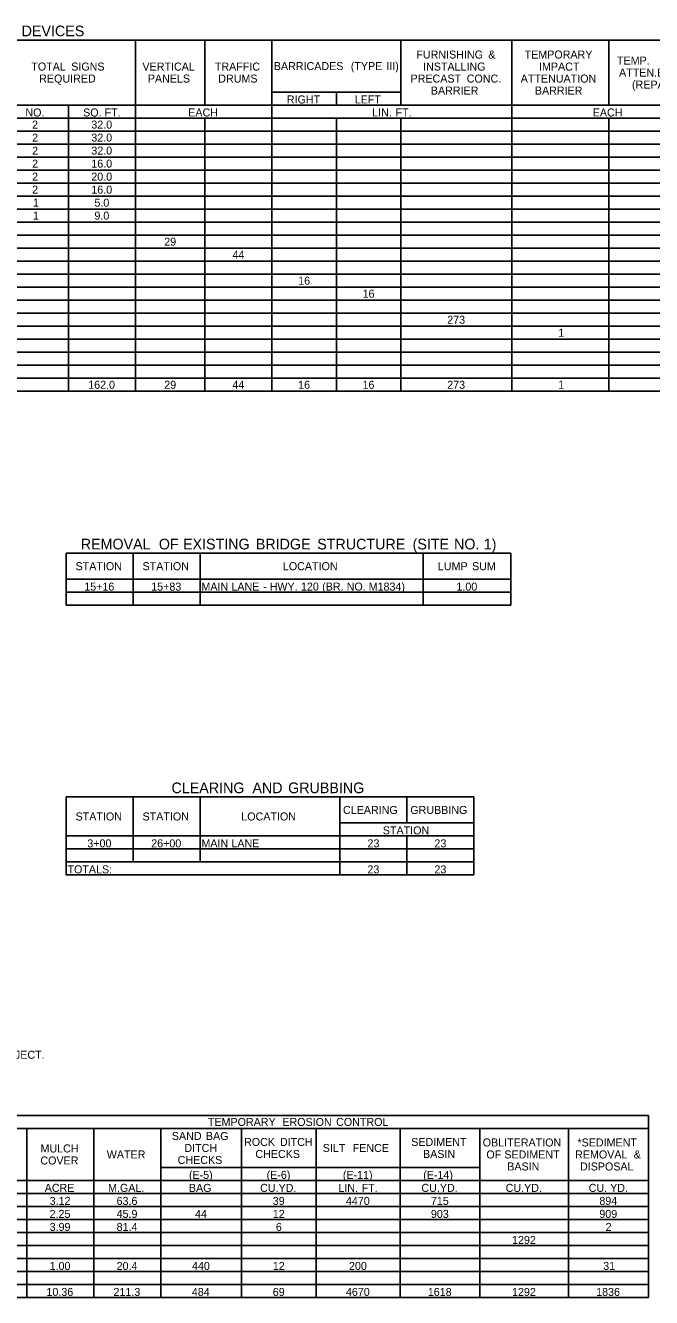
# Model space of a CAD drawing. Extents: x 1940653 to 1945779, y 534266 to 535271.
# Drawn here: x 1941239 to 1941662, y 534410 to 535268 of the extents above; entities that cross this region are included whole.
import ezdxf

# ---------------------------------------------------------------- set-up
doc = ezdxf.new("R2010")
doc.units = 0
doc.layers.add('Default', color=7, linetype='Continuous')
doc.layers.add('R_Logo', color=7, linetype='Continuous')

msp = doc.modelspace()

# ---------------------------------------------------------------- linework, layer by layer
at = {"layer": 'Default'}
for p, q in [((1940658.64, 535258.6), (1941697.16, 535258.6)), ((1941313.26, 535021.67), (1941313.26, 535258.6)), ((1941360.2, 535214.72), (1941360.2, 535258.6)), ((1941405.39, 535021.67), (1941405.39, 535258.6)), ((1941492.27, 535214.72), (1941492.27, 535258.6)), ((1941567.29, 535021.67), (1941567.29, 535258.6)), ((1941632.67, 535214.72), (1941632.67, 535258.6)), ((1941405.39, 535223.5), (1941492.27, 535223.5)), ((1941448.83, 535214.72), (1941448.83, 535223.5)), ((1941448.83, 535214.72), (1941448.83, 535223.5)), ((1941222.87, 535214.72), (1941697.16, 535214.72)), ((1941268.07, 535021.67), (1941268.07, 535214.72)), ((1941405.39, 535214.72), (1941448.83, 535214.72)), ((1941405.39, 535021.67), (1941405.39, 535214.72)), ((1941448.83, 535214.72), (1941697.16, 535214.72)), ((1941567.29, 535021.67), (1941567.29, 535214.72)), ((1941170.66, 535205.95), (1941697.16, 535205.95)), ((1941268.07, 535021.67), (1941268.07, 535205.95)), ((1941313.26, 535021.67), (1941313.26, 535205.95)), ((1941360.2, 535021.67), (1941360.2, 535205.95)), ((1941360.2, 535021.67), (1941360.2, 535205.95)), ((1941448.83, 535021.67), (1941448.83, 535205.95)), ((1941448.83, 535021.67), (1941448.83, 535205.95)), ((1941492.27, 535021.67), (1941492.27, 535205.95)), ((1941492.27, 535021.67), (1941492.27, 535205.95)), ((1941632.67, 535021.67), (1941632.67, 535205.95)), ((1941632.67, 535021.67), (1941632.67, 535205.95)), ((1940658.64, 535197.17), (1941697.16, 535197.17)), ((1940658.64, 535188.4), (1941697.16, 535188.4)), ((1940658.64, 535179.62), (1941697.16, 535179.62)), ((1940658.64, 535170.85), (1941697.16, 535170.85)), ((1940658.64, 535162.07), (1941697.16, 535162.07)), ((1940658.64, 535153.3), (1941697.16, 535153.3)), ((1940658.64, 535144.52), (1941697.16, 535144.52)), ((1940658.64, 535135.75), (1941697.16, 535135.75)), ((1940658.64, 535126.97), (1941697.16, 535126.97)), ((1940658.64, 535118.2), (1941697.16, 535118.2)), ((1940658.64, 535109.42), (1941697.16, 535109.42)), ((1940658.64, 535100.65), (1941697.16, 535100.65)), ((1940658.64, 535091.87), (1941697.16, 535091.87)), ((1940658.64, 535083.1), (1941697.16, 535083.1)), ((1940658.64, 535074.32), (1941697.16, 535074.32)), ((1940658.64, 535065.55), (1941697.16, 535065.55)), ((1940658.64, 535056.77), (1941697.16, 535056.77)), ((1940658.64, 535048), (1941697.16, 535048)), ((1940658.64, 535039.22), (1941697.16, 535039.22)), ((1940658.64, 535030.45), (1941697.16, 535030.45)), ((1940658.64, 535021.67), (1941697.16, 535021.67)), ((1941266.54, 534912.46), (1941566.65, 534912.46)), ((1941266.54, 534877.36), (1941266.54, 534912.46)), ((1941266.54, 534877.36), (1941266.54, 534912.46)), ((1941311.73, 534877.36), (1941311.73, 534912.46)), ((1941356.92, 534877.36), (1941356.92, 534912.46)), ((1941507.41, 534877.36), (1941507.41, 534912.46)), ((1941566.65, 534877.36), (1941566.65, 534912.46)), ((1941566.65, 534877.36), (1941566.65, 534912.46)), ((1941266.54, 534894.91), (1941566.65, 534894.91)), ((1941311.73, 534877.36), (1941311.73, 534894.91)), ((1941356.92, 534877.36), (1941356.92, 534894.91)), ((1941507.41, 534877.36), (1941507.41, 534894.91)), ((1941266.54, 534886.13), (1941566.65, 534886.13)), ((1941266.54, 534877.36), (1941566.65, 534877.36)), ((1941266.54, 534748.03), (1941541.64, 534748.03)), ((1941266.54, 534695.38), (1941266.54, 534748.03)), ((1941266.54, 534695.38), (1941266.54, 534748.03)), ((1941311.73, 534704.15), (1941311.73, 534748.03)), ((1941356.92, 534704.15), (1941356.92, 534748.03)), ((1941451.25, 534695.38), (1941451.25, 534748.03)), ((1941496.45, 534730.48), (1941496.45, 534748.03)), ((1941541.64, 534695.38), (1941541.64, 534748.03)), ((1941541.64, 534730.48), (1941541.64, 534748.03)), ((1941451.25, 534730.48), (1941541.64, 534730.48)), ((1941451.25, 534704.15), (1941451.25, 534730.48)), ((1941266.54, 534721.7), (1941541.64, 534721.7)), ((1941311.73, 534704.15), (1941311.73, 534721.7)), ((1941356.92, 534704.15), (1941356.92, 534721.7)), ((1941496.45, 534695.38), (1941496.45, 534721.7)), ((1941496.45, 534695.38), (1941496.45, 534721.7)), ((1941541.64, 534704.15), (1941541.64, 534721.7)), ((1941266.54, 534712.93), (1941541.64, 534712.93)), ((1941266.54, 534704.15), (1941541.64, 534704.15)), ((1941356.92, 534704.15), (1941541.64, 534704.15)), ((1941266.54, 534695.38), (1941541.64, 534695.38)), ((1940660.36, 534533.19), (1941659.39, 534533.19)), ((1941659.39, 534410.34), (1941659.39, 534533.19)), ((1940953.44, 534524.41), (1941659.39, 534524.41)), ((1941239.95, 534410.34), (1941239.95, 534524.41)), ((1941285.14, 534410.34), (1941285.14, 534524.41)), ((1941330.33, 534410.34), (1941330.33, 534524.41)), ((1941384.73, 534410.34), (1941384.73, 534524.41)), ((1941435.19, 534410.34), (1941435.19, 534524.41)), ((1941491.79, 534410.34), (1941491.79, 534524.41)), ((1941545.75, 534410.34), (1941545.75, 534524.41)), ((1941605.42, 534410.34), (1941605.42, 534524.41)), ((1941330.33, 534498.09), (1941545.75, 534498.09)), ((1941491.79, 534498.09), (1941545.75, 534498.09)), ((1940953.44, 534489.31), (1941545.75, 534489.31)), ((1941239.95, 534410.34), (1941239.95, 534489.31)), ((1941285.14, 534410.34), (1941285.14, 534489.31)), ((1941330.33, 534419.11), (1941330.33, 534489.31)), ((1941384.73, 534419.11), (1941384.73, 534489.31)), ((1941435.19, 534419.11), (1941435.19, 534489.31)), ((1941491.79, 534410.34), (1941491.79, 534489.31)), ((1941545.75, 534489.31), (1941659.39, 534489.31)), ((1941545.75, 534410.34), (1941545.75, 534489.31)), ((1941605.42, 534410.34), (1941605.42, 534489.31)), ((1940660.36, 534480.54), (1941659.39, 534480.54)), ((1941659.39, 534419.11), (1941659.39, 534480.54)), ((1940660.36, 534471.76), (1941659.39, 534471.76)), ((1940660.36, 534462.99), (1941659.39, 534462.99)), ((1940660.36, 534454.21), (1941659.39, 534454.21)), ((1940660.36, 534445.44), (1941659.39, 534445.44)), ((1940660.36, 534436.66), (1941659.39, 534436.66)), ((1940660.36, 534427.89), (1941659.39, 534427.89)), ((1941188.61, 534419.11), (1941435.19, 534419.11)), ((1941239.95, 534419.11), (1941435.19, 534419.11)), ((1941435.19, 534419.11), (1941659.39, 534419.11)), ((1941605.42, 534419.11), (1941659.39, 534419.11)), ((1940660.36, 534410.34), (1941659.39, 534410.34))]:
    msp.add_line(p, q, dxfattribs=at)
at = {"layer": 'R_Logo'}
for p, q in [((1941261.28, 534924.74), (1941261.28, 534924.74)), ((1941261.28, 534760.31), (1941261.28, 534760.31))]:
    msp.add_line(p, q, dxfattribs=at)

# ---------------------------------------------------------------- texts
at = {"layer": 'Default'}
for s, height, p in [(' DEVICES', 7.2, (1941233.82, 535261.14)), ('FURNISHING', 5.4, (1941502.82, 535246.11)), (' &', 5.4, (1941549.32, 535246.11)), ('TEMPORARY', 5.4, (1941575.87, 535246.11)), ('TEMP.', 5.4, (1941638.22, 535242.06)), ('TOTAL', 5.4, (1941243, 535238.01)), (' SIGNS', 5.4, (1941267.92, 535238.01)), ('VERTICAL', 5.4, (1941317.98, 535238.01)), ('TRAFFIC', 5.4, (1941366.86, 535238.01)), ('BARRICADES', 5.4, (1941406.64, 535238.35)), (' (TYPE', 5.4, (1941456.58, 535238.35)), (' III)', 5.4, (1941480.52, 535238.35)), ('INSTALLING', 5.4, (1941507.37, 535238.01)), ('IMPACT', 5.4, (1941585.6, 535238.01)), ('ATTEN.BARR.', 5.4, (1941639.6, 535233.96)), ('REQUIRED', 5.4, (1941248.34, 535229.91)), ('PANELS', 5.4, (1941321.61, 535229.91)), ('DRUMS', 5.4, (1941369.15, 535229.91)), ('PRECAST', 5.4, (1941498.88, 535229.91)), (' CONC.', 5.4, (1941534.79, 535229.91)), ('ATTENUATION', 5.4, (1941573.25, 535229.91)), ('(REPAIR)', 5.4, (1941648.34, 535225.86)), ('RIGHT', 5.4, (1941415.45, 535215.8)), ('LEFT', 5.4, (1941461.2, 535215.8)), ('BARRIER', 5.4, (1941512.61, 535221.81)), ('BARRIER', 5.4, (1941582.81, 535221.81)), ('NO.', 5.4, (1941239.02, 535207.03)), ('SQ.', 5.4, (1941277.98, 535207.03)), (' FT.', 5.4, (1941290.46, 535207.03)), ('EACH', 5.4, (1941348.92, 535207.03)), ('LIN.', 5.4, (1941473.03, 535207.03)), (' FT.', 5.4, (1941486.76, 535207.03)), ('EACH', 5.4, (1941621.83, 535207.03)), ('2', 5.4, (1941243.57, 535198.86)), ('32.0', 5.4, (1941283.5, 535198.86)), ('2', 5.4, (1941243.57, 535190.08)), ('32.0', 5.4, (1941283.5, 535190.08)), ('2', 5.4, (1941243.57, 535181.31)), ('32.0', 5.4, (1941283.5, 535181.31)), ('2', 5.4, (1941243.57, 535172.53)), ('16.0', 5.4, (1941283.5, 535172.53)), ('2', 5.4, (1941243.57, 535163.76)), ('20.0', 5.4, (1941283.5, 535163.76)), ('2', 5.4, (1941243.57, 535154.98)), ('16.0', 5.4, (1941283.5, 535154.98)), ('1', 5.4, (1941244.07, 535146.21)), ('5.0', 5.4, (1941285.6, 535146.21)), ('1', 5.4, (1941244.07, 535137.43)), ('9.0', 5.4, (1941285.6, 535137.43)), ('29', 5.4, (1941332.7, 535119.88)), ('44', 5.4, (1941378.79, 535111.11)), ('16', 5.4, (1941423.09, 535093.56)), ('16', 5.4, (1941466.53, 535084.78)), ('273', 5.4, (1941523.66, 535067.23)), ('1', 5.4, (1941598.58, 535058.46)), ('162.0', 5.4, (1941281.41, 535023.36)), ('29', 5.4, (1941332.71, 535023.36)), ('44', 5.4, (1941378.69, 535023.36)), ('16', 5.4, (1941423.05, 535023.36)), ('16', 5.4, (1941466.49, 535023.36)), ('273', 5.4, (1941523.65, 535023.36)), ('1', 5.4, (1941598.49, 535023.36)), ('REMOVAL', 7.2, (1941276.39, 534915)), (' OF', 7.2, (1941326.39, 534915)), (' EXISTING', 7.2, (1941342.69, 534915)), (' BRIDGE', 7.2, (1941391.83, 534915)), (' STRUCTURE', 7.2, (1941433.26, 534915)), (' (SITE', 7.2, (1941497.6, 534915)), (' NO.', 7.2, (1941525.6, 534915)), (' 1)', 7.2, (1941545.59, 534915)), ('STATION', 5.4, (1941272.88, 534900.98)), ('STATION', 5.4, (1941318.07, 534900.98)), ('LOCATION', 5.4, (1941412.77, 534900.98)), ('LUMP', 5.4, (1941517.35, 534900.98)), (' SUM', 5.4, (1941538.38, 534900.98)), ('15+16', 5.4, (1941278.72, 534887.21)), ('15+83', 5.4, (1941323.91, 534887.21)), ('MAIN', 5.4, (1941357.8, 534887.21)), (' LANE', 5.4, (1941376.05, 534887.21)), (' -', 5.4, (1941397.45, 534887.21)), (' HWY.', 5.4, (1941401.82, 534887.21)), (' 120', 5.4, (1941422.95, 534887.21)), (' (BR.', 5.4, (1941437.27, 534887.21)), (' NO.', 5.4, (1941453.79, 534887.21)), (' M1834)', 5.4, (1941468.64, 534887.21)), ('1.00', 5.4, (1941529.87, 534887.21)), ('CLEARING', 7.2, (1941337.6, 534750.57)), (' AND', 7.2, (1941389.53, 534750.57)), (' GRUBBING', 7.2, (1941413.62, 534750.57)), ('CLEARING', 5.4, (1941453.33, 534736.55)), ('GRUBBING', 5.4, (1941498.73, 534736.55)), ('STATION', 5.4, (1941272.88, 534732.16)), ('STATION', 5.4, (1941318.07, 534732.16)), ('LOCATION', 5.4, (1941384.69, 534732.16)), ('STATION', 5.4, (1941480.19, 534722.78)), ('3+00', 5.4, (1941280.82, 534714.01)), ('26+00', 5.4, (1941323.92, 534714.01)), ('MAIN', 5.4, (1941357.8, 534714.01)), (' LANE', 5.4, (1941376.05, 534714.01)), ('23', 5.4, (1941469.83, 534714.01)), ('23', 5.4, (1941515.02, 534714.01)), ('TOTALS:', 5.4, (1941267.42, 534696.46)), ('23', 5.4, (1941469.82, 534696.46)), ('23', 5.4, (1941515.01, 534696.46)), (' PROJECT.', 5.4, (1941214.31, 534571.41)), ('TEMPORARY', 5.4, (1941362.16, 534526.1)), (' EROSION', 5.4, (1941410.38, 534526.1)), (' CONTROL', 5.4, (1941446.67, 534526.1)), ('SAND', 5.4, (1941337.82, 534516.65)), (' BAG', 5.4, (1941358.83, 534516.65)), ('ROCK', 5.4, (1941386.57, 534512.6)), (' DITCH', 5.4, (1941408.78, 534512.6)), ('SEDIMENT', 5.4, (1941499.35, 534512.6)), ('OBLITERATION', 5.4, (1941547.6, 534512.26)), ('*SEDIMENT', 5.4, (1941611.52, 534512.26)), ('MULCH', 5.4, (1941249.21, 534508.21)), ('WATER', 5.4, (1941293.92, 534504.16)), ('DITCH', 5.4, (1941346.29, 534508.55)), ('CHECKS', 5.4, (1941394.21, 534504.5)), ('SILT', 5.4, (1941439.65, 534508.55)), ('  FENCE', 5.4, (1941455.84, 534508.55)), ('BASIN', 5.4, (1941507.33, 534504.5)), ('OF', 5.4, (1941550.06, 534504.16)), (' SEDIMENT', 5.4, (1941560.19, 534504.16)), ('REMOVAL', 5.4, (1941609.94, 534504.16)), (' &', 5.4, (1941647.45, 534504.16)), ('COVER', 5.4, (1941249.14, 534500.11)), ('CHECKS', 5.4, (1941341.78, 534500.45)), ('BASIN', 5.4, (1941564.15, 534496.06)), ('DISPOSAL', 5.4, (1941613.23, 534496.06)), ('(E-5)', 5.4, (1941349.35, 534490.39)), ('(E-6)', 5.4, (1941401.78, 534490.39)), ('(E-11)', 5.4, (1941453.21, 534490.39)), ('(E-14)', 5.4, (1941507.44, 534490.39)), ('ACRE', 5.4, (1941252.04, 534481.62)), ('M.GAL.', 5.4, (1941294.79, 534481.62)), ('BAG', 5.4, (1941349.37, 534481.62)), ('CU.YD.', 5.4, (1941397.43, 534481.62)), ('LIN.', 5.4, (1941450.18, 534481.62)), (' FT.', 5.4, (1941463.91, 534481.62)), ('CU.YD.', 5.4, (1941506.24, 534481.62)), ('CU.YD.', 5.4, (1941563.06, 534481.62)), ('CU.', 5.4, (1941619.09, 534481.62)), (' YD.', 5.4, (1941631.57, 534481.62)), ('3.12', 5.4, (1941255.4, 534472.84)), ('63.6', 5.4, (1941300.56, 534472.84)), ('39', 5.4, (1941405.93, 534472.84)), ('4470', 5.4, (1941455.28, 534472.84)), ('715', 5.4, (1941512.63, 534472.84)), ('894', 5.4, (1941626.3, 534472.84)), ('2.25', 5.4, (1941255.35, 534464.07)), ('45.9', 5.4, (1941300.56, 534464.07)), ('44', 5.4, (1941353.52, 534464.07)), ('12', 5.4, (1941405.97, 534464.07)), ('903', 5.4, (1941512.65, 534464.07)), ('909', 5.4, (1941626.28, 534464.07)), ('3.99', 5.4, (1941255.37, 534455.29)), ('81.4', 5.4, (1941300.58, 534455.29)), ('6', 5.4, (1941408.03, 534455.29)), ('2', 5.4, (1941630.51, 534455.29)), ('1292', 5.4, (1941567.4, 534446.52)), ('1.00', 5.4, (1941255.38, 534428.97)), ('20.4', 5.4, (1941300.58, 534428.97)), ('440', 5.4, (1941351.42, 534428.97)), ('12', 5.4, (1941405.97, 534428.97)), ('200', 5.4, (1941457.38, 534428.97)), ('31', 5.4, (1941628.91, 534428.97)), ('10.36', 5.4, (1941253.24, 534411.42)), ('211.3', 5.4, (1941298.46, 534411.42)), ('484', 5.4, (1941351.33, 534411.42)), ('69', 5.4, (1941405.94, 534411.42)), ('4670', 5.4, (1941455.29, 534411.42)), ('1618', 5.4, (1941510.55, 534411.42)), ('1292', 5.4, (1941567.39, 534411.42)), ('1836', 5.4, (1941624.15, 534411.42))]:
    msp.add_text(s, height=height, dxfattribs=at).set_placement(p)

doc.saveas('drawing.dxf')
